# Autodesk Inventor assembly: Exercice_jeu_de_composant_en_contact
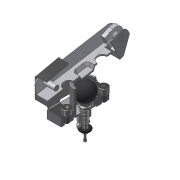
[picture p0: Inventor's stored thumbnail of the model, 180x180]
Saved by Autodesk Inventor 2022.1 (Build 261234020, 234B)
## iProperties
Created: 2018-06
Part Number: Exercice_jeu_de_composant_en_contact
Material: Générique
Document SubType Name: Assembly
Designer: Fabian Perrée
Mass: 316.677 g
Surface Area: 499.858 cm^2
Volume: 83.3782 cm^3
Density: 3.79808 g/cm^3
Author: Fabian Perrée
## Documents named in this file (4)
- C:\Users\fabia\Mon Drive\01_Giup\01_Clients\07_ENI\Manuscrit\Fichiers_exercice\Chapitre_06\Exercice_jeu_de_composant_en_contact\Exercice_jeu_de_composant_en_contact.iam
- C:\Users\fabia\Mon Drive\01_Giup\01_Clients\07_ENI\Manuscrit\Fichiers_exercice\Chapitre_06\Exercice_jeu_de_composant_en_contact\Composants\Ens_levier\Ens_levier.iam
- C:\Users\fabia\Mon Drive\01_Giup\01_Clients\07_ENI\Manuscrit\Fichiers_exercice\Chapitre_06\Exercice_jeu_de_composant_en_contact\Composants\Ens_chapeau\Ens_chapeau.iam
- C:\Users\fabia\Mon Drive\01_Giup\01_Clients\07_ENI\Manuscrit\Fichiers_exercice\Chapitre_06\Exercice_jeu_de_composant_en_contact\Composants\Ens_poussoir\Ens_poussoir.iam
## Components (3 placed, 3 different names)
1. Ens_levier:1 [sub-assembly] — Placage:26, Placage:27, Drive_Me, Placage:30
2. Ens_chapeau:1 [sub-assembly] — Placage:26, Placage:27, Drive_Me, Placage:30, Logement:1
3. Ens_poussoir:1 [sub-assembly] — Logement:1
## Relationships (5: Mate 3, Angle 1, Insert 1)
- Placage:26 [Mate]: Ens_levier:1 ↔ Ens_chapeau:1
- Placage:27 [Mate]: Ens_levier:1 ↔ Ens_chapeau:1
- Drive_Me [Angle]: Ens_levier:1 ↔ Ens_chapeau:1
- Placage:30 [Mate]: Ens_levier:1 ↔ Ens_chapeau:1
- Logement:1 [Insert]: Ens_chapeau:1 ↔ Ens_poussoir:1
